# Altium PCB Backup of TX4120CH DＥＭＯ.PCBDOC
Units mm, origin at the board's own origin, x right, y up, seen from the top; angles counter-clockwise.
Board outline 36.58 x 30.02 mm, 2 copper layers (Top Layer, Bottom Layer); 19 components, 13 nets, 49 pads, 67 vias.
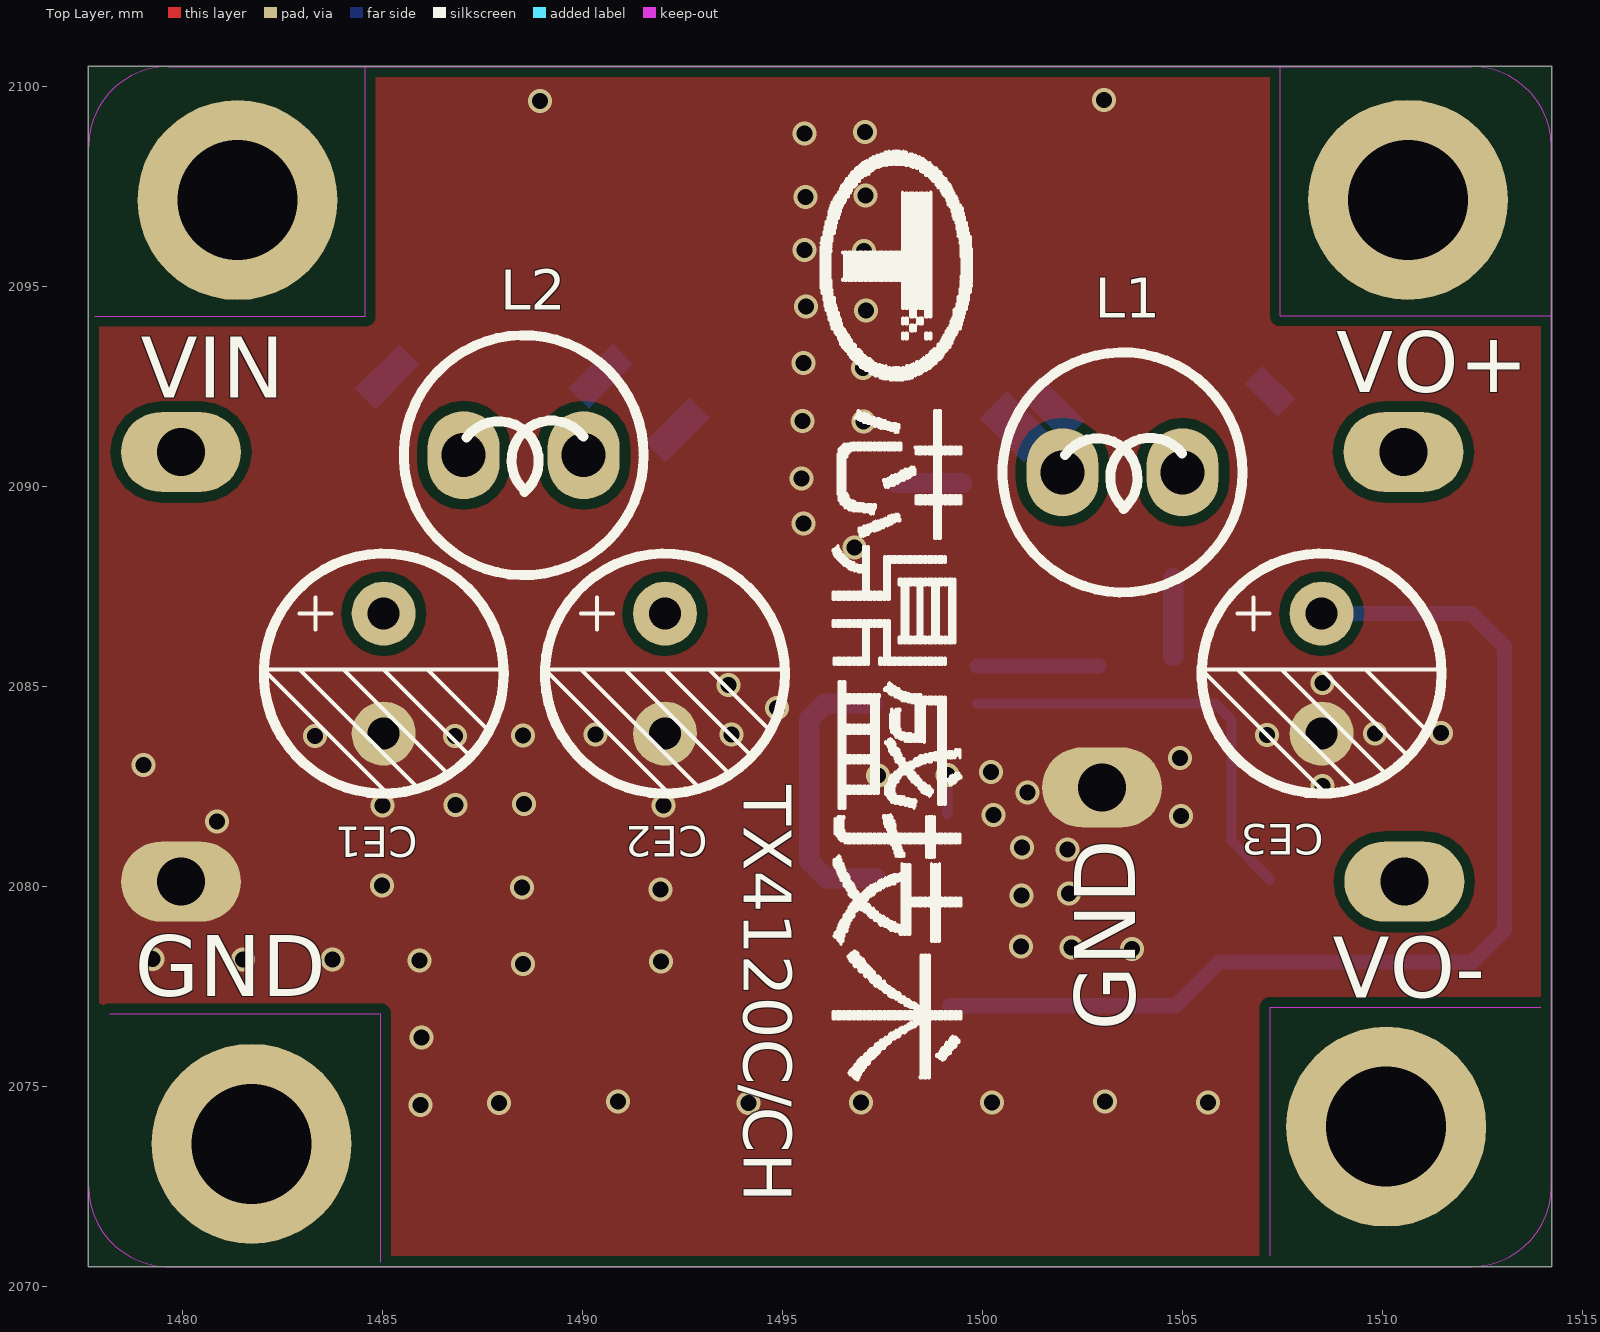
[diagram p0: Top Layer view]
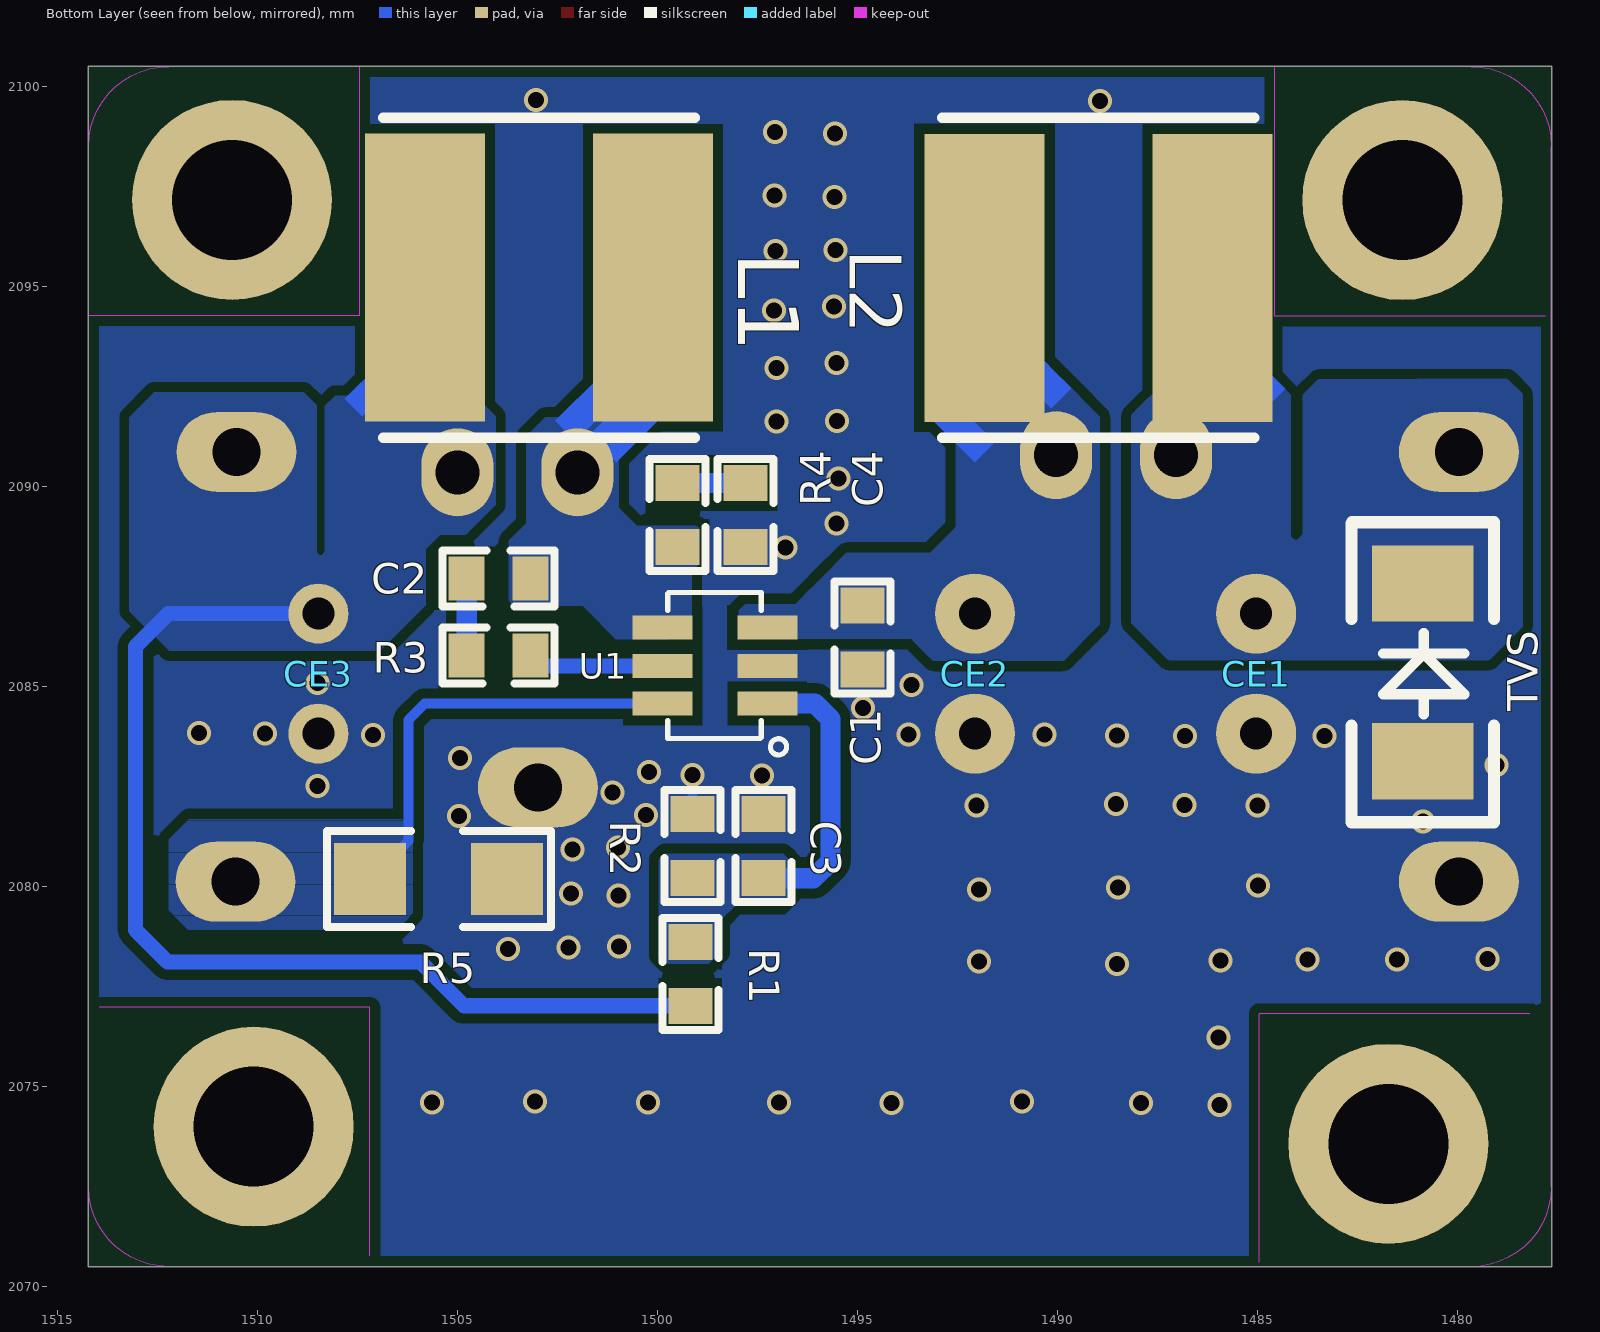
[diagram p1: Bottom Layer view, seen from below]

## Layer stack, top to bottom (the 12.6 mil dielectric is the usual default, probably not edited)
Top Layer: signal copper 0.0356
Dielectric: core 0.32, FR-4, Dk 4.8
Bottom Layer: signal copper 0.0356

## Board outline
1477.645,2070.485 1514.23,2070.485 1514.23,2100.5 1477.645,2100.5

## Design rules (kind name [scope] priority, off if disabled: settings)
Clearance [All] p1: gap=0.254
PolygonConnect [All] p1: connectstyle=Direct reliefconductorwidth=0.254 reliefentries=4 polygonreliefangle="90 Angle"
RoutingLayers [All] p1: top layer_v5=FALSE bottom layer_v5=FALSE
RoutingVias [All] p1: holewidth=0.711 width=1.27 viastyle="Through Hole" minholewidth=0.711 minwidth=1.27 maxholewidth=0.711 maxwidth=1.27
SilkscreenOverComponentPads [All] p1: minsilkscreentomaskgap=0.254
SolderMaskExpansion [All] p1: expansion=0.102
TestPointUsage FabricationTestPointUsage [All] p1: valid=0 allowmultiple=FALSE
Testpoint FabricationTestpoint [All] p1: side=3 testpointundercomponent=TRUE minsize=1.016 maxsize=2.54 preferedsize=1.524 minholesize=0 maxholesize=1.016 preferedholesize=0.813 testpointgrid=0.025 style=297 order=0123456789
Width [All] p1: maxlimit=0.254 minlimit=0.254 preferedwidth=0.254
22 further rules are at their usual default settings.

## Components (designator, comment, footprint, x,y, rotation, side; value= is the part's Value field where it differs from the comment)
C1 "1K" 0603 1495.013,2086.099 r90 bottom
C2 "1K" 0603 1504.094,2087.835 r180 bottom
C3 "1K" 0603 1497.479,2080.881 r90 bottom
C4 "1K" 0603 1497.66,2089.402 r270 bottom
CE1 "100uF/35V" C6#1 1484.728,2085.646 r270 bottom
CE2 "100uF/35V" C6#1 1491.76,2085.646 r270 bottom
CE3 "100uF/35V" C6#2 1508.177,2085.646 r270 bottom
L1 "" L03A 1505.002,2090.348 r180 top
L1 "Comment" 电感-(7x7.8x5)mm 1500.111,2095.214 r0 bottom
L2 "" L03A 1490.032,2090.776 r180 top
L2 "Comment" 电感-(7x7.8x5)mm 1491.828,2095.212 r180 bottom
R1 "1K" 0603 1499.315,2077.688 r90 bottom
R2 "1K" 0603 1499.257,2080.881 r90 bottom
R3 "1K" 0603 1504.094,2085.899 r180 bottom
R4 "1K" 0603 1499.362,2089.404 r270 bottom
R5 "40mR" 1206 1505.452,2080.045 r270 bottom
TVS "IN5822" M7 1480.861,2087.586 r90 bottom
TX4120C/CH "Comment" LOGO 1498.352,2095.498 r270 top
U1 "TX4120C/CH" SOT23-6L 1499.743,2084.578 r90 bottom

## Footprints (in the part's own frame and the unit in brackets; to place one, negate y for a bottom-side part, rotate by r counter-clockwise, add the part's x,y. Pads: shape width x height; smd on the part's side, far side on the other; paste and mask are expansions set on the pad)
0603 [mm]
  rect 0.9x1.1 smd: 1(0.923,-0.136) 2(-0.677,-0.136)
  silkscreen extent -1.28,-0.84 1.52,0.56
1206 [mm]
  rect 1.8x1.8 smd: 1(-0.132,1.688) 2(-0.132,-1.732)
  silkscreen extent -1.33,-2.81 1.07,2.79
C6#1 [mm]
  round 2 / inner round 1.6 / far side round 1.6 hole 0.8: 1(-1.17,-0.303) 2(1.83,-0.303)
C6#2 [mm]
  round 1.5 / inner round 1.6 / far side round 1.6 hole 0.8: 1(-1.17,-0.303) 2(1.83,-0.303)
L03A [mm]
  oval 1.8x2.2 hole 1.1: 1(0,0) 2(3,0)
  silkscreen extent -1.5,-3 4.5,3
LOGO [mm]
  silkscreen extent -2.88,-2.39 20.34,1.37
M7 [mm]
  rect 1.905x2.54 smd: 1(-4.463,0.007) 2(-0.018,0.007)
  silkscreen extent -5.99,-1.77 1.51,1.79
SOT23-6L [mm]
  rect 0.6x1.5 smd: 1(-0.01,-2.489) 2(0.93,-2.489) 3(1.895,-2.489) 4(1.895,0.127) 5(0.93,0.127) 6(-0.01,0.127)
  silkscreen extent -1.3,-2.97 2.77,0
电感-(7x7.8x5)mm [mm]
  rect 3x7.2 smd: 1(0,0) 2(5.7,0)
  silkscreen extent -1.05,-4 6.75,4

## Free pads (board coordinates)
  round 5 hole 3: 4(1481.378,2097.153) 4(1481.727,2073.561) 4(1510.094,2073.988) 4(1510.636,2097.16)
  oval 3x2 hole 1.2: 5(1479.964,2080.114) 5(1479.964,2090.858) 5(1502.989,2082.472) 5(1510.526,2090.858) 5(1510.547,2080.114)

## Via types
v1: diameter 0.6, hole 0.4, Top Layer to Bottom Layer, 53 vias
v2: diameter 0.6, hole 0.4, Top Layer to Bottom Layer, tented both sides, 14 vias

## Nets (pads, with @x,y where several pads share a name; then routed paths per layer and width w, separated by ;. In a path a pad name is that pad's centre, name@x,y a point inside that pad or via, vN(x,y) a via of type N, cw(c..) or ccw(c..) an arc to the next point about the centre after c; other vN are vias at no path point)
12V: CE1.1 L2.2 pad.5@1479.964,2090.858 TVS.2
BST: R3.1 U1.5 | length 3
  Bottom Layer w0.381: U1.5 R3.1@1502.916,2085.508
BST2: C2.2 R3.2 | length 1.9
  Bottom Layer w0.508: R3.2 C2.2
CS: pad.5@1510.547,2080.114 R5.2 U1.6 | length 10.9
  Bottom Layer w0.254: U1.6 1505.816,2084.568 1506.225,2084.159 1506.225,2081.136 R5.2
FB: C3.2 R1.1 R2.2 U1.1 | length 7.1
  Bottom Layer w0.508: U1.1 1496.06,2084.568 1495.673,2084.181 1495.673,2080.631 1496.1,2080.204 C3.2
GND: C1.2 C3.1 C4.1 CE1.2 CE2.2 CE3.2 pad.5@1479.964,2080.114 pad.5@1502.989,2082.472 R2.1 R5.1 TVS.1 U1.2 | length 1
  Bottom Layer w0.254: R2.1 v1(1499.121,2082.786)
  other v1: 1485.945,2074.535 1487.908,2074.578 1494.155,2074.578 1496.962,2074.599 1500.234,2074.599 1505.637,2074.599 1490.884,2074.62 1503.062,2074.62 1485.97,2076.216 1488.514,2078.062 1491.962,2078.119 1485.924,2078.144 1483.75,2078.166 1503.735,2078.432 1502.229,2078.466 1500.959,2078.495 1491.957,2079.925 1488.484,2079.974 1484.987,2080.017 1480.867,2081.618 1504.966,2081.754 1484.996,2082.024 1492.02,2082.024 1486.822,2082.035 1488.54,2082.058 1508.496,2082.508 1497.383,2082.766 1500.216,2082.851 1479.02,2083.033 1504.936,2083.201 1483.318,2083.754 1486.817,2083.754 1488.517,2083.763 1490.33,2083.793 1493.724,2083.793 1507.117,2083.785 1509.814,2083.818 1511.459,2083.826 1494.865,2084.46 1493.65,2085.034 1508.496,2085.082 1496.795,2088.475 1497.028,2091.623 1495.506,2091.631 1497.019,2092.954 1495.521,2093.087 1495.574,2097.228 1497.076,2097.263 1495.557,2098.817 1497.06,2098.852 1488.941,2099.637 1503.034,2099.662
  other v2: 1479.254,2078.187 1481.512,2078.166 1500.977,2079.775 1502.16,2079.82 1502.123,2080.922 1500.984,2080.966 1500.282,2081.777 1501.123,2082.341 1495.521,2089.074 1495.476,2090.196 1497.09,2094.399 1495.586,2094.494 1497.044,2095.881 1495.551,2095.908
LED: 
LED2: 
NetC1_1: C1.1 CE2.1 L2.1 U1.3
NetC3_1: CE3.1 L1.1@1505.002,2090.348 L1.2@1505.811,2095.214 pad.5@1510.526,2090.858 R1.2 | length 26.7
  Bottom Layer w0.381: R1.2 1504.83,2077.011 1505.923,2078.104 1512.248,2078.104 1513.051,2078.907 1513.051,2085.993 1512.228,2086.816 CE3.1
R6-2: 
RC: C4.2 R4.2 | length 1.7
  Bottom Layer w0.508: C4.2@1497.847,2090.081 R4.2
SW: C2.1 L1.1@1500.111,2095.214 L1.2@1502.002,2090.348 R4.1 U1.4

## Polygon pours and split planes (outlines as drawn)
GND on Top Layer "TopLayer-No Net" (solid, remove dead copper, pour order 1000): 1477.599,2100.649 1514.111,2100.649 1514.156,2100.604 1514.291,2100.469 1514.291,2070.652 1477.78,2070.652 1477.599,2070.471
GND on Bottom Layer "Bottom Layer-GND" (solid, remove dead copper, pour order 1000): 1478.544,2103.309 1512.572,2103.309 1516.202,2099.679 1516.202,2071.13 1513.165,2068.093 1479.974,2068.093 1475.193,2072.874 1475.193,2099.958
NetC3_1 on Bottom Layer "Bottom Layer-NetC3_1" (hatched Horizontal grid 0.025 track 0.025, remove dead copper, pour order 1001): 1477.419,2101.785
NetC3_1 on Bottom Layer "Bottom Layer-NetC3_1 1" (solid, remove dead copper, pour order 1002): 1504.046,2089.538 1504.046,2091.754 1504.561,2092.269 1508.059,2092.269 1508.313,2092.015 1508.313,2088.36 1508.392,2088.281 1508.448,2088.281 1508.514,2088.347 1508.514,2092.02 1508.846,2092.352 1512.579,2092.352 1513.2,2091.731 1513.2,2086.881 1512.205,2085.886 1506.926,2085.886 1505.792,2087.02 1505.792,2088.43 1505.43,2088.792 1504.792,2088.792
CS on Bottom Layer "Bottom Layer-CS" (hatched Horizontal grid 0.025 track 0.025, remove dead copper, pour order 1003): 1506.219,2079.213 1506.123,2079.309 1506.123,2081.403 1506.393,2081.673 1511.708,2081.673 1512.222,2081.159 1512.222,2079.396 1511.725,2078.899 1506.527,2078.899 1506.217,2079.209
NetC1_1 on Bottom Layer "Bottom Layer-NetC1_1" (solid, remove dead copper, pour order 1004): 1491.352,2092.701 1489.903,2092.701 1488.944,2091.742 1488.944,2086.541 1489.85,2085.635 1493.106,2085.635 1493.655,2086.184 1497.842,2086.184 1497.982,2086.324 1497.974,2086.332 1497.974,2086.891 1497.817,2087.048 1496.56,2087.048 1495.269,2088.339 1493.184,2088.339 1492.538,2088.985 1492.538,2092.284 1492.129,2092.693 1491.395,2092.693
12V on Bottom Layer "Bottom Layer-12V" (solid, remove dead copper, pour order 1005): 1481.002,2092.685 1478.751,2092.685 1478.367,2092.301 1478.367,2086.491 1479.205,2085.653 1487.231,2085.653 1488.156,2086.578 1488.156,2091.778 1487.275,2092.659 1484.535,2092.659 1484.169,2092.293 1484.169,2088.75 1484.082,2088.663 1484.003,2088.663 1483.864,2088.802 1483.864,2092.284 1483.472,2092.676 1481.002,2092.676
SW on Bottom Layer "Bottom Layer-SW" (solid, remove dead copper, pour order 1006): 1499.144,2086.202 1499.144,2087.869 1498.952,2088.061 1498.952,2088.95 1499.013,2089.011 1500.522,2089.011 1500.968,2089.457 1500.968,2091.324 1501.369,2091.725 1502.808,2091.725 1503.279,2091.254 1503.279,2089.081 1503.724,2088.636 1503.724,2087.144 1503.593,2087.013 1501.874,2087.013 1501.037,2086.176 1499.746,2086.176 1499.393,2086.529
12V on Bottom Layer "Bottom Layer-12V 1" (solid, remove dead copper, pour order 1007): 1498.015,2086.151
FB on Bottom Layer "Bottom Layer-FB" (solid, remove dead copper, pour order 1008): 1496.744,2080.703 1496.858,2080.817 1499.814,2080.817 1499.963,2080.668 1499.963,2078.277 1499.746,2078.06 1498.715,2078.06 1498.445,2078.33 1498.445,2079.133 1498.035,2079.543 1496.91,2079.543 1496.648,2079.805 1496.648,2080.603 1496.744,2080.699
LED on Bottom Layer "Bottom Layer-LED" (hatched Horizontal grid 0.025 track 0.025, remove dead copper, pour order 1009): 1502.432,2081.627
FB on Bottom Layer "Bottom Layer-FB 1" (hatched Horizontal grid 0.025 track 0.025, remove dead copper, pour order 1010): 1496.441,2084.832

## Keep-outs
Keep-Out Layer:
  lines w0.013: 1477.652,2072.491 1477.652,2098.494 cw(c1479.652,2098.494) 1479.652,2100.494 1486.224,2100.494 1512.224,2100.494 cw(c1512.224,2098.494) 1514.224,2098.494 1514.224,2072.494 cw(c1512.224,2072.494) 1512.224,2070.494 1486.224,2070.494 1479.574,2070.494 ; 1477.654,2072.491 ccw(c1479.654,2072.491) 1479.654,2070.491 ; 1477.801,2094.256 1484.571,2094.256 1484.571,2100.468 ; 1478.188,2076.814 1484.958,2076.814 1484.958,2070.602 ; 1507.189,2070.759 1507.189,2076.971 1513.959,2076.971 ; 1507.443,2100.475 1507.443,2094.263 1514.213,2094.263

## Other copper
Bottom Layer:
  region net 12V: 1485.416,2093.54 1484.31,2092.434 1484.813,2091.93 1485.92,2093.037
  region net NetC1_1: 1492.672,2092.21 1491.566,2091.104 1492.069,2090.6 1493.176,2091.707
  region net NetC1_1: 1490.757,2093.557 1489.65,2092.451 1490.153,2091.947 1491.26,2093.054
  region net SW: 1501.71,2091.276 1500.606,2092.381 1499.93,2091.706 1501.035,2090.601
  region net SW: 1502.555,2091.632 1501.449,2092.739 1500.945,2092.236 1502.052,2091.129
  region net NetC3_1: 1507.821,2092.182 1506.997,2093.006 1506.558,2092.567 1507.367,2091.758 1507.397,2091.758

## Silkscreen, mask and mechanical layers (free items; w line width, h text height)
Top Overlay:
  text "VO+" at 1508.846,2092.352 h1.52
  text "VIN" at 1478.962,2092.209 h1.52
  text "GND" at 1478.806,2077.246 h1.52
  text "VO-" at 1508.755,2077.216 h1.52
  text "GND" at 1503.817,2076.385 h1.52 r90
Bottom Overlay:
